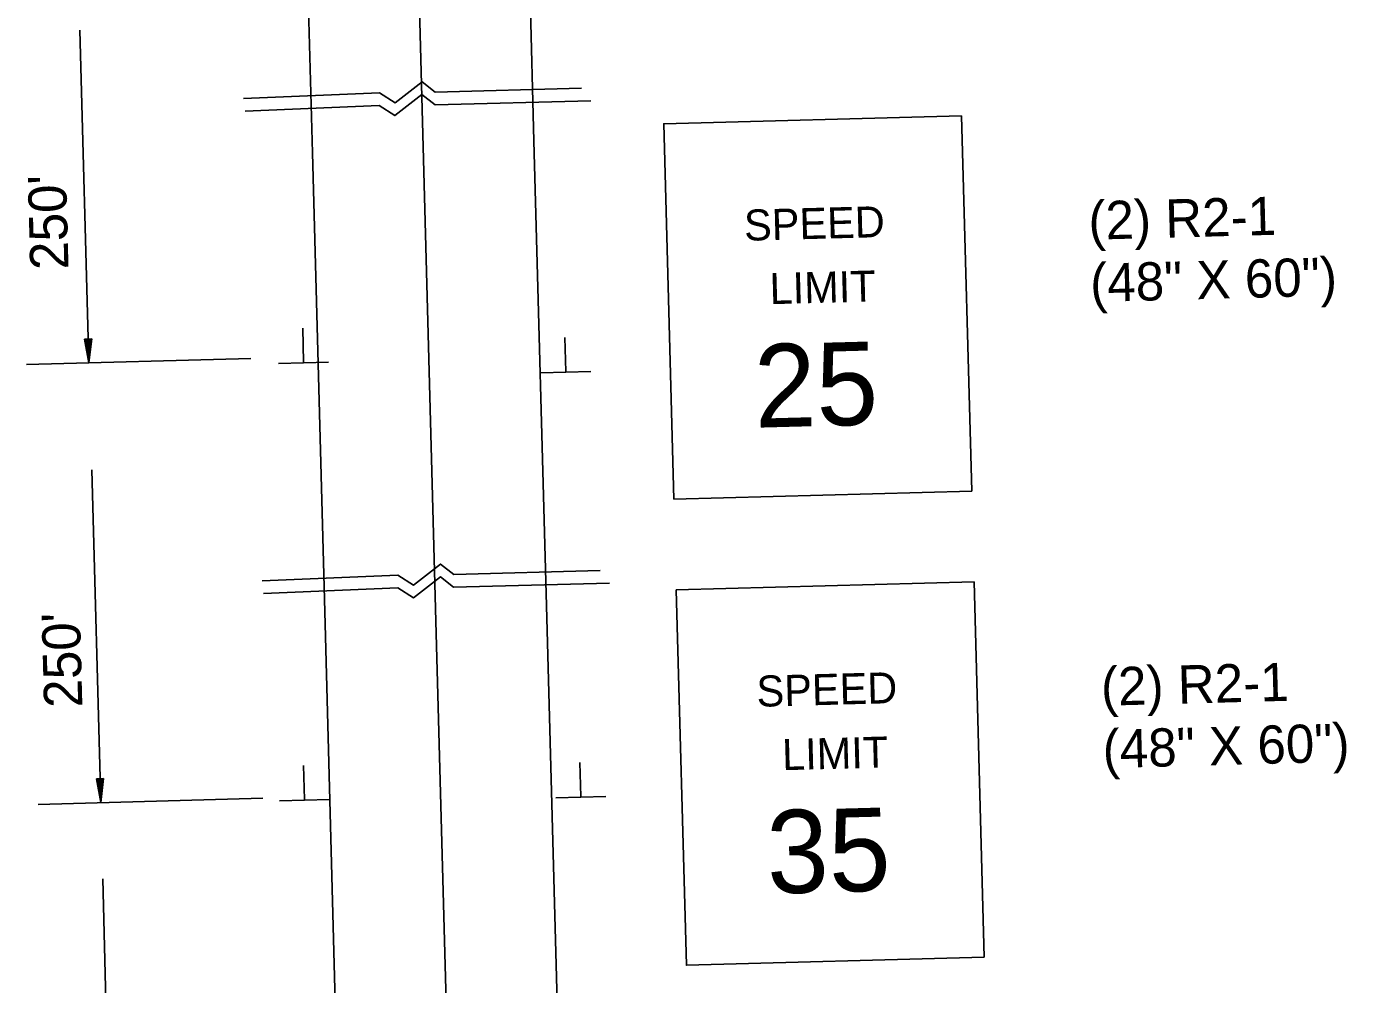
# Model space of a CAD drawing. Extents: x 1926836 to 1933254, y 596317 to 604524.
# Drawn here: x 1930891.9 to 1931103.7, y 598378.3 to 598532.1 of the extents above; entities that cross this region are included whole.
import ezdxf

# ---------------------------------------------------------------- set-up
doc = ezdxf.new("R2010")
doc.units = 0
doc.layers.add('Default', color=7, linetype='Continuous')

msp = doc.modelspace()

# ---------------------------------------------------------------- linework, layer by layer
at = {"layer": 'Default'}
for p, q in [((1930937.76, 598511.79), (1930936.06, 598575.19)), ((1930955.53, 598512.74), (1930953.85, 598575.32)), ((1930973.3, 598513.69), (1930971.65, 598575.45)), ((1930901.9, 598478.09), (1930900.47, 598531.47)), ((1930975.36, 598437.12), (1930973.3, 598513.69)), ((1930939.79, 598436.16), (1930937.76, 598511.79)), ((1930957.58, 598436.64), (1930955.53, 598512.74)), ((1930936.36, 598478.2), (1930936.21, 598483.66)), ((1930902.37, 598481.94), (1930901.22, 598481.91)), ((1930901.22, 598481.91), (1930901.9, 598478.09)), ((1930901.32, 598481.91), (1930901.88, 598478.73)), ((1930901.42, 598481.92), (1930901.87, 598479.39)), ((1930901.51, 598481.92), (1930901.85, 598480.03)), ((1930901.61, 598481.92), (1930901.83, 598480.68)), ((1930901.71, 598481.93), (1930901.81, 598481.32)), ((1930901.89, 598481.93), (1930901.81, 598481.32)), ((1930901.98, 598481.93), (1930901.83, 598480.68)), ((1930902.08, 598481.94), (1930901.85, 598480.03)), ((1930902.18, 598481.94), (1930901.87, 598479.39)), ((1930902.28, 598481.94), (1930901.88, 598478.73)), ((1930902.37, 598481.94), (1930901.9, 598478.09)), ((1930978.42, 598476.69), (1930978.27, 598482.16)), ((1930891.89, 598477.82), (1930927.9, 598478.79)), ((1930940.34, 598478.19), (1930932.34, 598477.98)), ((1930982.4, 598476.68), (1930974.4, 598476.47)), ((1930903.8, 598407.51), (1930902.36, 598460.89)), ((1930977.25, 598366.53), (1930975.36, 598437.12)), ((1930941.69, 598365.58), (1930939.79, 598436.16)), ((1930959.47, 598366.06), (1930957.58, 598436.64)), ((1930936.5, 598408.02), (1930936.36, 598413.48)), ((1930980.83, 598408.52), (1930980.68, 598413.98)), ((1930904.27, 598411.36), (1930903.12, 598411.33)), ((1930903.12, 598411.33), (1930903.8, 598407.51)), ((1930903.21, 598411.33), (1930903.78, 598408.15)), ((1930903.31, 598411.33), (1930903.76, 598408.81)), ((1930903.41, 598411.34), (1930903.74, 598409.45)), ((1930903.5, 598411.34), (1930903.73, 598410.1)), ((1930903.6, 598411.34), (1930903.71, 598410.74)), ((1930903.78, 598411.35), (1930903.71, 598410.74)), ((1930903.88, 598411.35), (1930903.73, 598410.1)), ((1930903.98, 598411.35), (1930903.74, 598409.45)), ((1930904.07, 598411.35), (1930903.76, 598408.81)), ((1930904.17, 598411.36), (1930903.78, 598408.15)), ((1930904.27, 598411.36), (1930903.8, 598407.51)), ((1930893.78, 598407.24), (1930929.8, 598408.21)), ((1930940.49, 598408.01), (1930932.48, 598407.79)), ((1930984.81, 598408.51), (1930976.81, 598408.29)), ((1930905.56, 598341.88), (1930904.12, 598395.26))]:
    msp.add_line(p, q, dxfattribs=at)
for points in [[(1930926.73, 598520.49), (1930948.51, 598521.41), (1930951.03, 598519.81), (1930955.37, 598523.17), (1930957.46, 598521.52), (1930980.95, 598522.14)], [(1930926.98, 598518.45), (1930948.48, 598519.36), (1930951, 598517.76), (1930955.34, 598521.12), (1930957.43, 598519.47), (1930982.45, 598520.14)], [(1930929.69, 598443.1), (1930951.48, 598444.02), (1930953.99, 598442.42), (1930958.33, 598445.78), (1930960.43, 598444.13), (1930983.92, 598444.76)], [(1930929.94, 598441.07), (1930951.45, 598441.97), (1930953.96, 598440.38), (1930958.3, 598443.73), (1930960.39, 598442.08), (1930985.41, 598442.75)]]:
    msp.add_lwpolyline(points, dxfattribs=at)
for points in [[(1931041.9, 598517.72), (1931043.52, 598457.5), (1930995.74, 598456.22), (1930994.12, 598516.44)], [(1931043.91, 598442.93), (1931045.52, 598382.72), (1930997.75, 598381.43), (1930996.13, 598441.65)]]:
    msp.add_lwpolyline(points, close=True, dxfattribs=at)

# ---------------------------------------------------------------- texts
for s, height, rotation, p in [("250'", 6.14, 91.5377, (1930898.65, 598493.09)), ('(2) R2-1', 6.14, 1.5377, (1931062.33, 598497.83)), ('SPEED', 4.978, 1.5377, (1931007.07, 598497.67)), ('(48" X 60")', 6.1396, 1.5377, (1931062.6, 598487.83)), ('LIMIT', 4.978, 1.5377, (1931011.16, 598487.49)), ('25', 13.342, 1.5377, (1931008.8, 598467.67)), ("250'", 6.14, 91.5377, (1930900.87, 598422.83)), ('SPEED', 4.978, 1.5377, (1931009.07, 598422.89)), ('(2) R2-1', 6.14, 1.5377, (1931064.34, 598423.05)), ('(48" X 60")', 6.1396, 1.5377, (1931064.61, 598413.04)), ('LIMIT', 4.978, 1.5377, (1931013.17, 598412.71)), ('35', 13.342, 1.5377, (1931010.8, 598392.89))]:
    msp.add_text(s, height=height, rotation=rotation, dxfattribs=at).set_placement(p)

doc.saveas('drawing.dxf')
